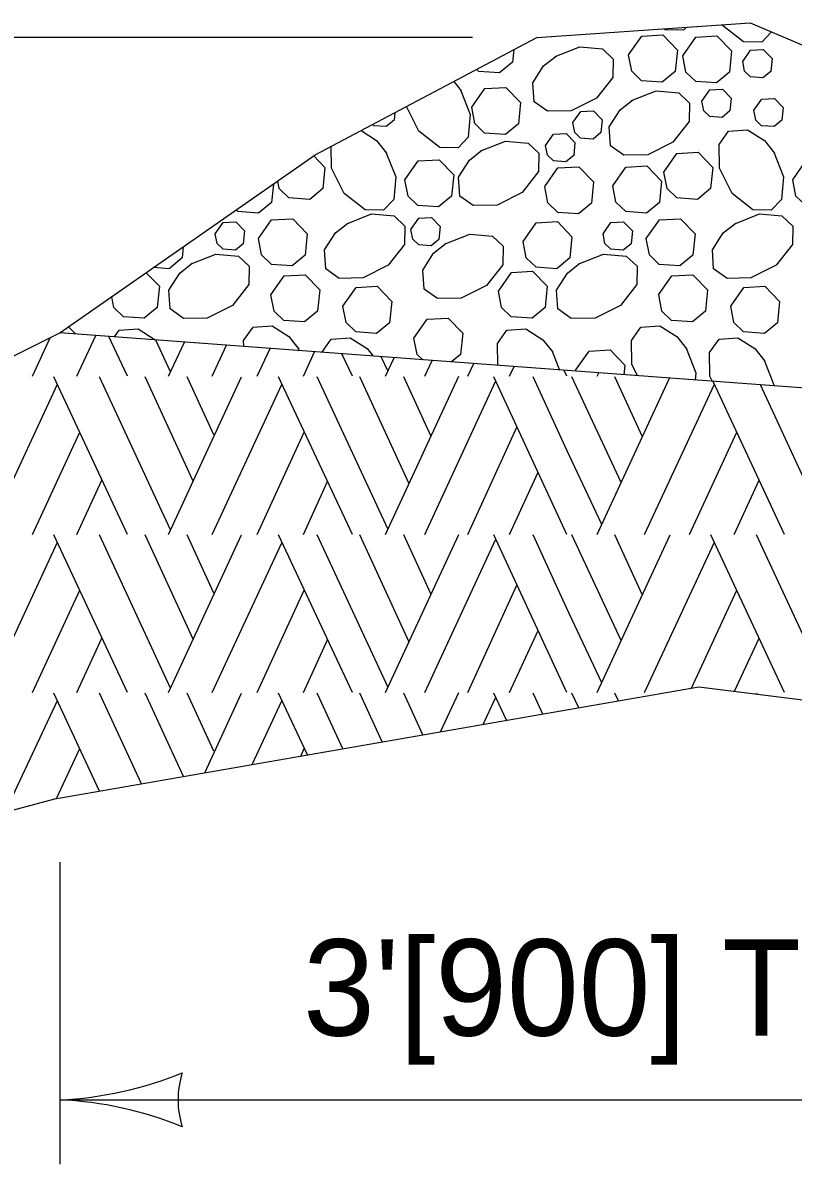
# Model space of a CAD drawing. Extents: x 49991.4 to 50021, y 49987.6 to 50011.4.
# Drawn here: x 50011.779 to 50012.259, y 49989.263 to 49989.973 of the extents above; entities that cross this region are included whole.
import ezdxf

# ---------------------------------------------------------------- set-up
doc = ezdxf.new("R2010")
doc.units = 0
for name, color, linetype in [('Level 1', 7, 'Continuous'), ('Level 2', 7, 'Continuous'), ('Level 3', 7, 'Continuous')]:
    doc.layers.add(name, color=color, linetype=linetype)

msp = doc.modelspace()

# ---------------------------------------------------------------- linework, layer by layer
at = {"layer": 'Level 1'}
for p, q in [((50011.78534, 49989.75325), (50011.79646, 49989.77722)), ((50012.64299, 49989.71774), (50011.80249, 49989.78024)), ((50011.81308, 49989.75325), (50011.82471, 49989.77858)), ((50011.84447, 49989.75325), (50011.83296, 49989.77797)), ((50011.87129, 49989.756), (50011.86212, 49989.7758)), ((50011.87007, 49989.75325), (50011.87989, 49989.77448)), ((50011.8972, 49989.75325), (50011.90615, 49989.77253)), ((50011.92524, 49989.75325), (50011.93317, 49989.77052)), ((50011.95389, 49989.75325), (50011.96079, 49989.76846)), ((50011.98437, 49989.75325), (50011.97783, 49989.7672)), ((50012.00662, 49989.7563), (50012.00241, 49989.76537)), ((50012.0051, 49989.75325), (50012.01042, 49989.76477)), ((50012.02948, 49989.75325), (50012.03399, 49989.76302)), ((50012.05631, 49989.75325), (50012.05989, 49989.7611)), ((50012.08222, 49989.75325), (50012.08495, 49989.75923)), ((50012.11788, 49989.75325), (50012.11618, 49989.75691)), ((50012.13677, 49989.75325), (50012.13772, 49989.75531)), ((50011.7573, 49989.65481), (50011.80088, 49989.74838)), ((50011.84447, 49989.65481), (50011.79875, 49989.75295)), ((50011.87129, 49989.65755), (50011.8271, 49989.75295)), ((50011.88531, 49989.68803), (50011.85544, 49989.75295)), ((50011.87007, 49989.65481), (50011.91549, 49989.75295)), ((50011.89812, 49989.71668), (50011.88166, 49989.75295)), ((50011.8972, 49989.65481), (50011.94048, 49989.74807)), ((50011.98437, 49989.65481), (50011.93835, 49989.75295)), ((50012.00662, 49989.65785), (50011.96243, 49989.75295)), ((50012.01973, 49989.6862), (50011.98894, 49989.75295)), ((50012.0051, 49989.65481), (50012.05052, 49989.75325)), ((50012.03345, 49989.71577), (50012.01638, 49989.75295)), ((50012.02948, 49989.65481), (50012.07338, 49989.7499)), ((50012.11788, 49989.65481), (50012.07246, 49989.75295)), ((50012.11788, 49989.70723), (50012.09684, 49989.75295)), ((50012.15171, 49989.68711), (50012.12092, 49989.75295)), ((50012.13677, 49989.65481), (50012.18176, 49989.75203)), ((50012.16482, 49989.71546), (50012.14774, 49989.75295)), ((50012.16603, 49989.65481), (50012.20962, 49989.74838)), ((50012.25321, 49989.65481), (50012.20885, 49989.75002)), ((50012.28003, 49989.65755), (50012.2382, 49989.74784)), ((50012.05631, 49989.65481), (50012.08679, 49989.72156)), ((50011.78534, 49989.65481), (50011.8149, 49989.71851)), ((50011.92524, 49989.65481), (50011.9545, 49989.71851)), ((50012.19408, 49989.65481), (50012.22364, 49989.71851)), ((50012.13952, 49989.6609), (50012.11788, 49989.70723)), ((50012.08222, 49989.65481), (50012.09989, 49989.69351)), ((50011.81308, 49989.65481), (50011.82862, 49989.68864)), ((50011.95389, 49989.65481), (50011.96883, 49989.68772)), ((50012.22181, 49989.65481), (50012.23736, 49989.68864)), ((50012.0051, 49989.55636), (50012.05052, 49989.65481)), ((50011.7573, 49989.55636), (50011.80088, 49989.64993)), ((50011.84447, 49989.55636), (50011.79875, 49989.6545)), ((50011.87129, 49989.5591), (50011.8271, 49989.6545)), ((50011.88531, 49989.58958), (50011.85544, 49989.6545)), ((50011.87007, 49989.55636), (50011.91549, 49989.6545)), ((50011.89812, 49989.61823), (50011.88166, 49989.6545)), ((50011.8972, 49989.55636), (50011.94048, 49989.64963)), ((50011.98437, 49989.55636), (50011.93835, 49989.6545)), ((50012.00662, 49989.55941), (50011.96243, 49989.6545)), ((50012.01973, 49989.58775), (50011.98894, 49989.6545)), ((50012.03345, 49989.61732), (50012.01638, 49989.6545)), ((50012.02948, 49989.55636), (50012.07338, 49989.65145)), ((50012.11788, 49989.55636), (50012.07246, 49989.6545)), ((50012.11788, 49989.60878), (50012.09684, 49989.6545)), ((50012.15171, 49989.58867), (50012.12092, 49989.6545)), ((50012.13677, 49989.55636), (50012.18219, 49989.6545)), ((50012.16482, 49989.61701), (50012.14774, 49989.6545)), ((50012.16603, 49989.55636), (50012.20962, 49989.64993)), ((50012.25321, 49989.55636), (50012.20749, 49989.6545)), ((50012.28003, 49989.5591), (50012.23583, 49989.6545)), ((50011.78534, 49989.55636), (50011.8149, 49989.62006)), ((50011.92524, 49989.55636), (50011.9545, 49989.62006)), ((50012.05631, 49989.55636), (50012.08679, 49989.62311)), ((50012.19534, 49989.55909), (50012.22364, 49989.62006)), ((50012.13952, 49989.56245), (50012.11788, 49989.60878)), ((50012.08222, 49989.55636), (50012.09989, 49989.59507)), ((50011.81308, 49989.55636), (50011.82862, 49989.59019)), ((50011.95389, 49989.55636), (50011.96883, 49989.58927)), ((50012.22218, 49989.55716), (50012.23736, 49989.59019)), ((50011.82718, 49989.49503), (50011.79875, 49989.55605)), ((50011.79934, 49989.49018), (50012.19999, 49989.5599)), ((50011.85327, 49989.49957), (50011.8271, 49989.55605)), ((50011.87935, 49989.5041), (50011.85544, 49989.55605)), ((50011.89812, 49989.51978), (50011.88166, 49989.55605)), ((50011.89251, 49989.50639), (50011.91549, 49989.55605)), ((50011.95642, 49989.51752), (50011.93835, 49989.55605)), ((50011.97855, 49989.52137), (50011.96243, 49989.55605)), ((50012.00298, 49989.52562), (50011.98894, 49989.55605)), ((50012.02833, 49989.53003), (50012.01638, 49989.55605)), ((50012.03925, 49989.53193), (50012.05052, 49989.55636)), ((50012.08032, 49989.53908), (50012.07246, 49989.55605)), ((50012.10285, 49989.543), (50012.09684, 49989.55605)), ((50012.12521, 49989.54689), (50012.12092, 49989.55605)), ((50012.14996, 49989.55119), (50012.14774, 49989.55605)), ((50012.19999, 49989.5599), (50012.58758, 49989.51197)), ((50012.23612, 49989.55543), (50012.23583, 49989.55605)), ((50011.76848, 49989.48192), (50011.80088, 49989.55148)), ((50011.92209, 49989.51154), (50011.94048, 49989.55118)), ((50012.06578, 49989.53655), (50012.07338, 49989.55301)), ((50011.8004, 49989.49037), (50011.8149, 49989.52161)), ((50011.95229, 49989.5168), (50011.9545, 49989.52161)), ((50011.24627, 49989.34203), (50011.79934, 49989.49018))]:
    msp.add_line(p, q, dxfattribs=at)
for points in [[(50011.04469, 49989.40134), (50011.80249, 49989.78024), (50011.96129, 49989.89104), (50012.09909, 49989.96404), (50012.23179, 49989.97324), (50012.38279, 49989.90914), (50012.46764, 49989.84469), (50012.55249, 49989.78024), (50012.64299, 49989.71774), (50013.29239, 49989.74544), (50013.56379, 49989.78024), (50014.06739, 49989.78024)], [(50012.19216, 49989.97049), (50012.19048, 49989.96873), (50012.17905, 49989.96894), (50012.1783, 49989.96953)], [(50012.24508, 49989.9676), (50012.23908, 49989.96129), (50012.22765, 49989.9615), (50012.21466, 49989.97167), (50012.21447, 49989.97204)], [(50012.15621, 49989.95325), (50012.1644, 49989.96491), (50012.17749, 49989.96566), (50012.18659, 49989.95623), (50012.18527, 49989.94301), (50012.17719, 49989.93629), (50012.16427, 49989.93722), (50012.15819, 49989.94311), (50012.15622, 49989.95324)], [(50012.18993, 49989.95275), (50012.19812, 49989.96441), (50012.21121, 49989.96516), (50012.22031, 49989.95573), (50012.21899, 49989.94251), (50012.2109, 49989.93579), (50012.19799, 49989.93672), (50012.19191, 49989.94262), (50012.18993, 49989.95275)], [(50012.08481, 49989.95647), (50012.08405, 49989.94878), (50012.07596, 49989.94206), (50012.06304, 49989.943), (50012.06175, 49989.94425)], [(50012.11049, 49989.95218), (50012.12582, 49989.95826), (50012.13991, 49989.95704), (50012.1466, 49989.95068), (50012.14639, 49989.93925), (50012.13623, 49989.92626), (50012.12052, 49989.91841), (50012.10573, 49989.91815), (50012.0974, 49989.92407), (50012.09661, 49989.93586), (50012.10337, 49989.9464), (50012.11111, 49989.95257)], [(50012.22722, 49989.94915), (50012.23214, 49989.95615), (50012.23999, 49989.9566), (50012.24545, 49989.95093), (50012.24466, 49989.94301), (50012.23981, 49989.93897), (50012.23206, 49989.93953), (50012.22841, 49989.94307), (50012.22722, 49989.94915)], [(50012.04741, 49989.93666), (50012.05205, 49989.93084)], [(50012.05863, 49989.92067), (50012.06683, 49989.93233), (50012.07991, 49989.93307), (50012.08901, 49989.92364), (50012.08769, 49989.91043), (50012.07961, 49989.9037), (50012.06669, 49989.90464), (50012.06061, 49989.91053), (50012.05863, 49989.92067)], [(50012.20185, 49989.92455), (50012.20677, 49989.93155), (50012.21462, 49989.932), (50012.22008, 49989.92634), (50012.21929, 49989.91841), (50012.21444, 49989.91437), (50012.20669, 49989.91494), (50012.20304, 49989.91847), (50012.20186, 49989.92455)], [(50012.05166, 49989.93146), (50012.05774, 49989.91613), (50012.05652, 49989.90204), (50012.05016, 49989.89534), (50012.03873, 49989.89556), (50012.02574, 49989.90572), (50012.01805, 49989.9211)], [(50012.15806, 49989.92479), (50012.1734, 49989.93087), (50012.18748, 49989.92965), (50012.19418, 49989.92329), (50012.19396, 49989.91186), (50012.1838, 49989.89887), (50012.1681, 49989.89102), (50012.1533, 49989.89076), (50012.14497, 49989.89668), (50012.14418, 49989.90847), (50012.15094, 49989.91901), (50012.15868, 49989.92518)], [(50012.23414, 49989.91879), (50012.23906, 49989.92578), (50012.24691, 49989.92623), (50012.25237, 49989.92057), (50012.25158, 49989.91265), (50012.24673, 49989.90861), (50012.23898, 49989.90917), (50012.23532, 49989.91271), (50012.23414, 49989.91878)], [(50012.12152, 49989.9111), (50012.12644, 49989.9181), (50012.1343, 49989.91855), (50012.13975, 49989.91289), (50012.13897, 49989.90496), (50012.13411, 49989.90092), (50012.12636, 49989.90148), (50012.12271, 49989.90502), (50012.12153, 49989.9111)], [(50012.01079, 49989.91726), (50012.01033, 49989.91265), (50012.00549, 49989.90861), (50011.99773, 49989.90917), (50011.99695, 49989.90993)], [(50011.98978, 49989.90613), (50011.9995, 49989.8999), (50012.00568, 49989.89216)], [(50012.10461, 49989.89688), (50012.10953, 49989.90388), (50012.11739, 49989.90432), (50012.12284, 49989.89867), (50012.12206, 49989.89074), (50012.1172, 49989.8867), (50012.10945, 49989.88726), (50012.1058, 49989.8908), (50012.10462, 49989.89688)], [(50012.24652, 49989.89278), (50012.25261, 49989.87745), (50012.25139, 49989.86336), (50012.24502, 49989.85667), (50012.23359, 49989.85688), (50012.2206, 49989.86704), (50012.21276, 49989.88274), (50012.2125, 49989.89754), (50012.21841, 49989.90587), (50012.2302, 49989.90666), (50012.24074, 49989.8999), (50012.24692, 49989.89216)], [(50012.00528, 49989.89278), (50012.01136, 49989.87745), (50012.01014, 49989.86336), (50012.00378, 49989.85667), (50011.99235, 49989.85688), (50011.97936, 49989.86704), (50011.97151, 49989.88274), (50011.97127, 49989.89632)], [(50012.06436, 49989.89356), (50012.07969, 49989.89964), (50012.09378, 49989.89842), (50012.10047, 49989.89205), (50012.10026, 49989.88062), (50012.09009, 49989.86764), (50012.0744, 49989.85979), (50012.0596, 49989.85952), (50012.05127, 49989.86544), (50012.05048, 49989.87723), (50012.05724, 49989.88777), (50012.06498, 49989.89395)], [(50011.96039, 49989.89041), (50011.96728, 49989.88326), (50011.96597, 49989.87005), (50011.95788, 49989.86332), (50011.94496, 49989.86426), (50011.93888, 49989.87016), (50011.93798, 49989.87477)], [(50012.17814, 49989.88029), (50012.18634, 49989.89195), (50012.19943, 49989.8927), (50012.20853, 49989.88326), (50012.20721, 49989.87005), (50012.19912, 49989.86332), (50012.1862, 49989.86426), (50012.18013, 49989.87016), (50012.17815, 49989.88029)], [(50012.01709, 49989.87558), (50012.02529, 49989.88724), (50012.03838, 49989.88799), (50012.04747, 49989.87856), (50012.04615, 49989.86534), (50012.03807, 49989.85862), (50012.02515, 49989.85955), (50012.01907, 49989.86544), (50012.0171, 49989.87558)], [(50012.10407, 49989.87126), (50012.11226, 49989.88291), (50012.12535, 49989.88366), (50012.13445, 49989.87423), (50012.13313, 49989.86101), (50012.12505, 49989.85429), (50012.11212, 49989.85523), (50012.10605, 49989.86112), (50012.10408, 49989.87125)], [(50012.14635, 49989.87174), (50012.15455, 49989.8834), (50012.16764, 49989.88415), (50012.17674, 49989.87472), (50012.17542, 49989.86149), (50012.16734, 49989.85477), (50012.15441, 49989.85571), (50012.14833, 49989.8616), (50012.14637, 49989.87173)], [(50012.25833, 49989.87558), (50012.26653, 49989.88724), (50012.27962, 49989.88799), (50012.28871, 49989.87856), (50012.2874, 49989.86534), (50012.27931, 49989.85862), (50012.26639, 49989.85955), (50012.26031, 49989.86544), (50012.25834, 49989.87558)], [(50011.93531, 49989.87291), (50011.93418, 49989.86149), (50011.92609, 49989.85477), (50011.91317, 49989.85571), (50011.91212, 49989.85673)], [(50011.98098, 49989.84821), (50011.99631, 49989.85429), (50012.01039, 49989.85307), (50012.01709, 49989.84671), (50012.01688, 49989.83528), (50012.00672, 49989.82229), (50011.99102, 49989.81444), (50011.97621, 49989.81418), (50011.96789, 49989.8201), (50011.96709, 49989.83189), (50011.97386, 49989.84243), (50011.9816, 49989.84861)], [(50012.22222, 49989.84821), (50012.23756, 49989.85429), (50012.25164, 49989.85307), (50012.25833, 49989.84671), (50012.25812, 49989.83528), (50012.24796, 49989.82229), (50012.23226, 49989.81444), (50012.21746, 49989.81418), (50012.20913, 49989.8201), (50012.20834, 49989.83189), (50012.2151, 49989.84243), (50012.22284, 49989.84861)], [(50011.89911, 49989.84191), (50011.90403, 49989.84891), (50011.91188, 49989.84936), (50011.91735, 49989.84369), (50011.91655, 49989.83577), (50011.91171, 49989.83173), (50011.90395, 49989.83229), (50011.9003, 49989.83583), (50011.89912, 49989.84191)], [(50011.92598, 49989.83889), (50011.93417, 49989.85055), (50011.94726, 49989.85129), (50011.95635, 49989.84186), (50011.95504, 49989.82865), (50011.94695, 49989.82192), (50011.93404, 49989.82286), (50011.92795, 49989.82875), (50011.92598, 49989.83889)], [(50012.02082, 49989.8446), (50012.02574, 49989.8516), (50012.0336, 49989.85204), (50012.03905, 49989.84639), (50012.03827, 49989.83846), (50012.03341, 49989.83442), (50012.02566, 49989.83498), (50012.02201, 49989.83852), (50012.02083, 49989.8446)], [(50012.09062, 49989.83712), (50012.09882, 49989.84878), (50012.11191, 49989.84953), (50012.12101, 49989.84009), (50012.11969, 49989.82687), (50012.11161, 49989.82015), (50012.09868, 49989.82109), (50012.09261, 49989.82698), (50012.09063, 49989.83712)], [(50012.14036, 49989.84191), (50012.14527, 49989.84891), (50012.15313, 49989.84936), (50012.15859, 49989.84369), (50012.1578, 49989.83577), (50012.15295, 49989.83173), (50012.14519, 49989.83229), (50012.14154, 49989.83583), (50012.14036, 49989.84191)], [(50012.16722, 49989.83889), (50012.17541, 49989.85055), (50012.1885, 49989.85129), (50012.1976, 49989.84186), (50012.19628, 49989.82865), (50012.1882, 49989.82192), (50012.17528, 49989.82286), (50012.1692, 49989.82875), (50012.16723, 49989.83889)], [(50012.04206, 49989.83562), (50012.05739, 49989.8417), (50012.07148, 49989.84049), (50012.07818, 49989.83412), (50012.07796, 49989.82269), (50012.0678, 49989.8097), (50012.0521, 49989.80185), (50012.0373, 49989.80159), (50012.02898, 49989.80751), (50012.02818, 49989.8193), (50012.03494, 49989.82984), (50012.04269, 49989.83602)], [(50011.87913, 49989.83371), (50011.87845, 49989.82687), (50011.87036, 49989.82015), (50011.8607, 49989.82085)], [(50011.88412, 49989.82323), (50011.89945, 49989.82931), (50011.91354, 49989.82809), (50011.92023, 49989.82172), (50011.92002, 49989.81029), (50011.90986, 49989.79731), (50011.89416, 49989.78946), (50011.87936, 49989.78919), (50011.87103, 49989.79511), (50011.87024, 49989.8069), (50011.877, 49989.81744), (50011.88474, 49989.82362)], [(50012.12537, 49989.82323), (50012.1407, 49989.82931), (50012.15478, 49989.82809), (50012.16148, 49989.82172), (50012.16126, 49989.81029), (50012.1511, 49989.79731), (50012.1354, 49989.78946), (50012.1206, 49989.78919), (50012.11227, 49989.79511), (50012.11148, 49989.8069), (50012.11825, 49989.81744), (50012.12599, 49989.82362)], [(50012.0752, 49989.80627), (50012.0834, 49989.81793), (50012.09648, 49989.81868), (50012.10558, 49989.80924), (50012.10427, 49989.79603), (50012.09618, 49989.7893), (50012.08326, 49989.79024), (50012.07718, 49989.79614), (50012.07521, 49989.80627)], [(50011.85619, 49989.8177), (50011.86434, 49989.80924), (50011.86302, 49989.79603), (50011.85494, 49989.7893), (50011.84202, 49989.79024), (50011.83594, 49989.79614), (50011.83466, 49989.80268)], [(50011.93369, 49989.80398), (50011.94188, 49989.81565), (50011.95497, 49989.81639), (50011.96406, 49989.80696), (50011.96275, 49989.79374), (50011.95466, 49989.78702), (50011.94175, 49989.78795), (50011.93567, 49989.79385), (50011.93369, 49989.80398)], [(50012.17493, 49989.80398), (50012.18312, 49989.81565), (50012.19621, 49989.81639), (50012.20531, 49989.80696), (50012.20399, 49989.79374), (50012.19591, 49989.78702), (50012.18299, 49989.78795), (50012.17691, 49989.79385), (50012.17494, 49989.80398)], [(50011.9785, 49989.79685), (50011.98669, 49989.8085), (50011.99978, 49989.80925), (50012.00888, 49989.79982), (50012.00756, 49989.7866), (50011.99948, 49989.77987), (50011.98656, 49989.78081), (50011.98048, 49989.78671), (50011.97851, 49989.79684)], [(50012.21974, 49989.79685), (50012.22794, 49989.8085), (50012.24102, 49989.80925), (50012.25012, 49989.79982), (50012.2488, 49989.7866), (50012.24072, 49989.77987), (50012.2278, 49989.78081), (50012.22172, 49989.78671), (50012.21975, 49989.79684)], [(50011.8079, 49989.78401), (50011.81178, 49989.77999), (50011.81174, 49989.77955)], [(50011.83637, 49989.77772), (50011.83933, 49989.78187), (50011.85112, 49989.78266), (50011.86166, 49989.77591), (50011.86172, 49989.77583)], [(50011.91678, 49989.77174), (50011.91671, 49989.77553), (50011.92263, 49989.78386), (50011.93442, 49989.78465), (50011.94496, 49989.77789), (50011.95114, 49989.77015)], [(50012.02264, 49989.77702), (50012.03084, 49989.78868), (50012.04392, 49989.78942), (50012.05302, 49989.77999), (50012.05171, 49989.76677), (50012.04611, 49989.76212)], [(50012.07489, 49989.75998), (50012.07465, 49989.77355), (50012.08057, 49989.78187), (50012.09236, 49989.78266), (50012.1029, 49989.77591), (50012.10908, 49989.76816)], [(50012.16182, 49989.75352), (50012.15822, 49989.76073), (50012.15795, 49989.77553), (50012.16387, 49989.78386), (50012.17566, 49989.78465), (50012.1862, 49989.77789), (50012.19238, 49989.77015)], [(50011.96533, 49989.76813), (50011.97123, 49989.77642), (50011.98301, 49989.77721), (50011.99356, 49989.77046), (50011.99731, 49989.76575)], [(50012.02815, 49989.76346), (50012.02462, 49989.76688), (50012.02265, 49989.77702)], [(50012.20843, 49989.75005), (50012.20681, 49989.7533), (50012.20655, 49989.76809), (50012.21247, 49989.77642), (50012.22425, 49989.77721), (50012.2348, 49989.77046), (50012.24098, 49989.76271)], [(50011.95075, 49989.77077), (50011.95138, 49989.76916)], [(50012.10868, 49989.76879), (50012.11331, 49989.75712)], [(50012.12341, 49989.75718), (50012.1316, 49989.76885), (50012.14469, 49989.76959), (50012.15379, 49989.76016), (50012.15319, 49989.75416)], [(50012.19199, 49989.77077), (50012.19807, 49989.75544), (50012.19767, 49989.75085)], [(50012.24058, 49989.76333), (50012.24666, 49989.748), (50012.24659, 49989.74721)], [(50012.12357, 49989.75636), (50012.12341, 49989.75718)]]:
    msp.add_lwpolyline(points, dxfattribs=at)
at = {"layer": 'Level 3'}
for p, q in [((50012.05909, 49989.96404), (50011.56326, 49989.96404)), ((50011.80249, 49989.45073), (50011.80249, 49989.26281)), ((50011.80249, 49989.30281), (50012.64299, 49989.30281))]:
    msp.add_line(p, q, dxfattribs=at)
for centre, radius, start, end in [((50011.791, 49989.53552), 0.233, 272.82731, 292.07716), ((50011.93071, 49989.30281), 0.05477, 162.13882, 197.86118), ((50011.79334, 49989.08067), 0.22232, 67.45601, 87.63952)]:
    msp.add_arc(centre, radius, start, end, dxfattribs=at)

# ---------------------------------------------------------------- texts
at = {"layer": 'Level 2'}
msp.add_text("3'[900] TYP.", height=0.06, dxfattribs=at).set_placement((50011.95373, 49989.34281))

doc.saveas('drawing.dxf')
